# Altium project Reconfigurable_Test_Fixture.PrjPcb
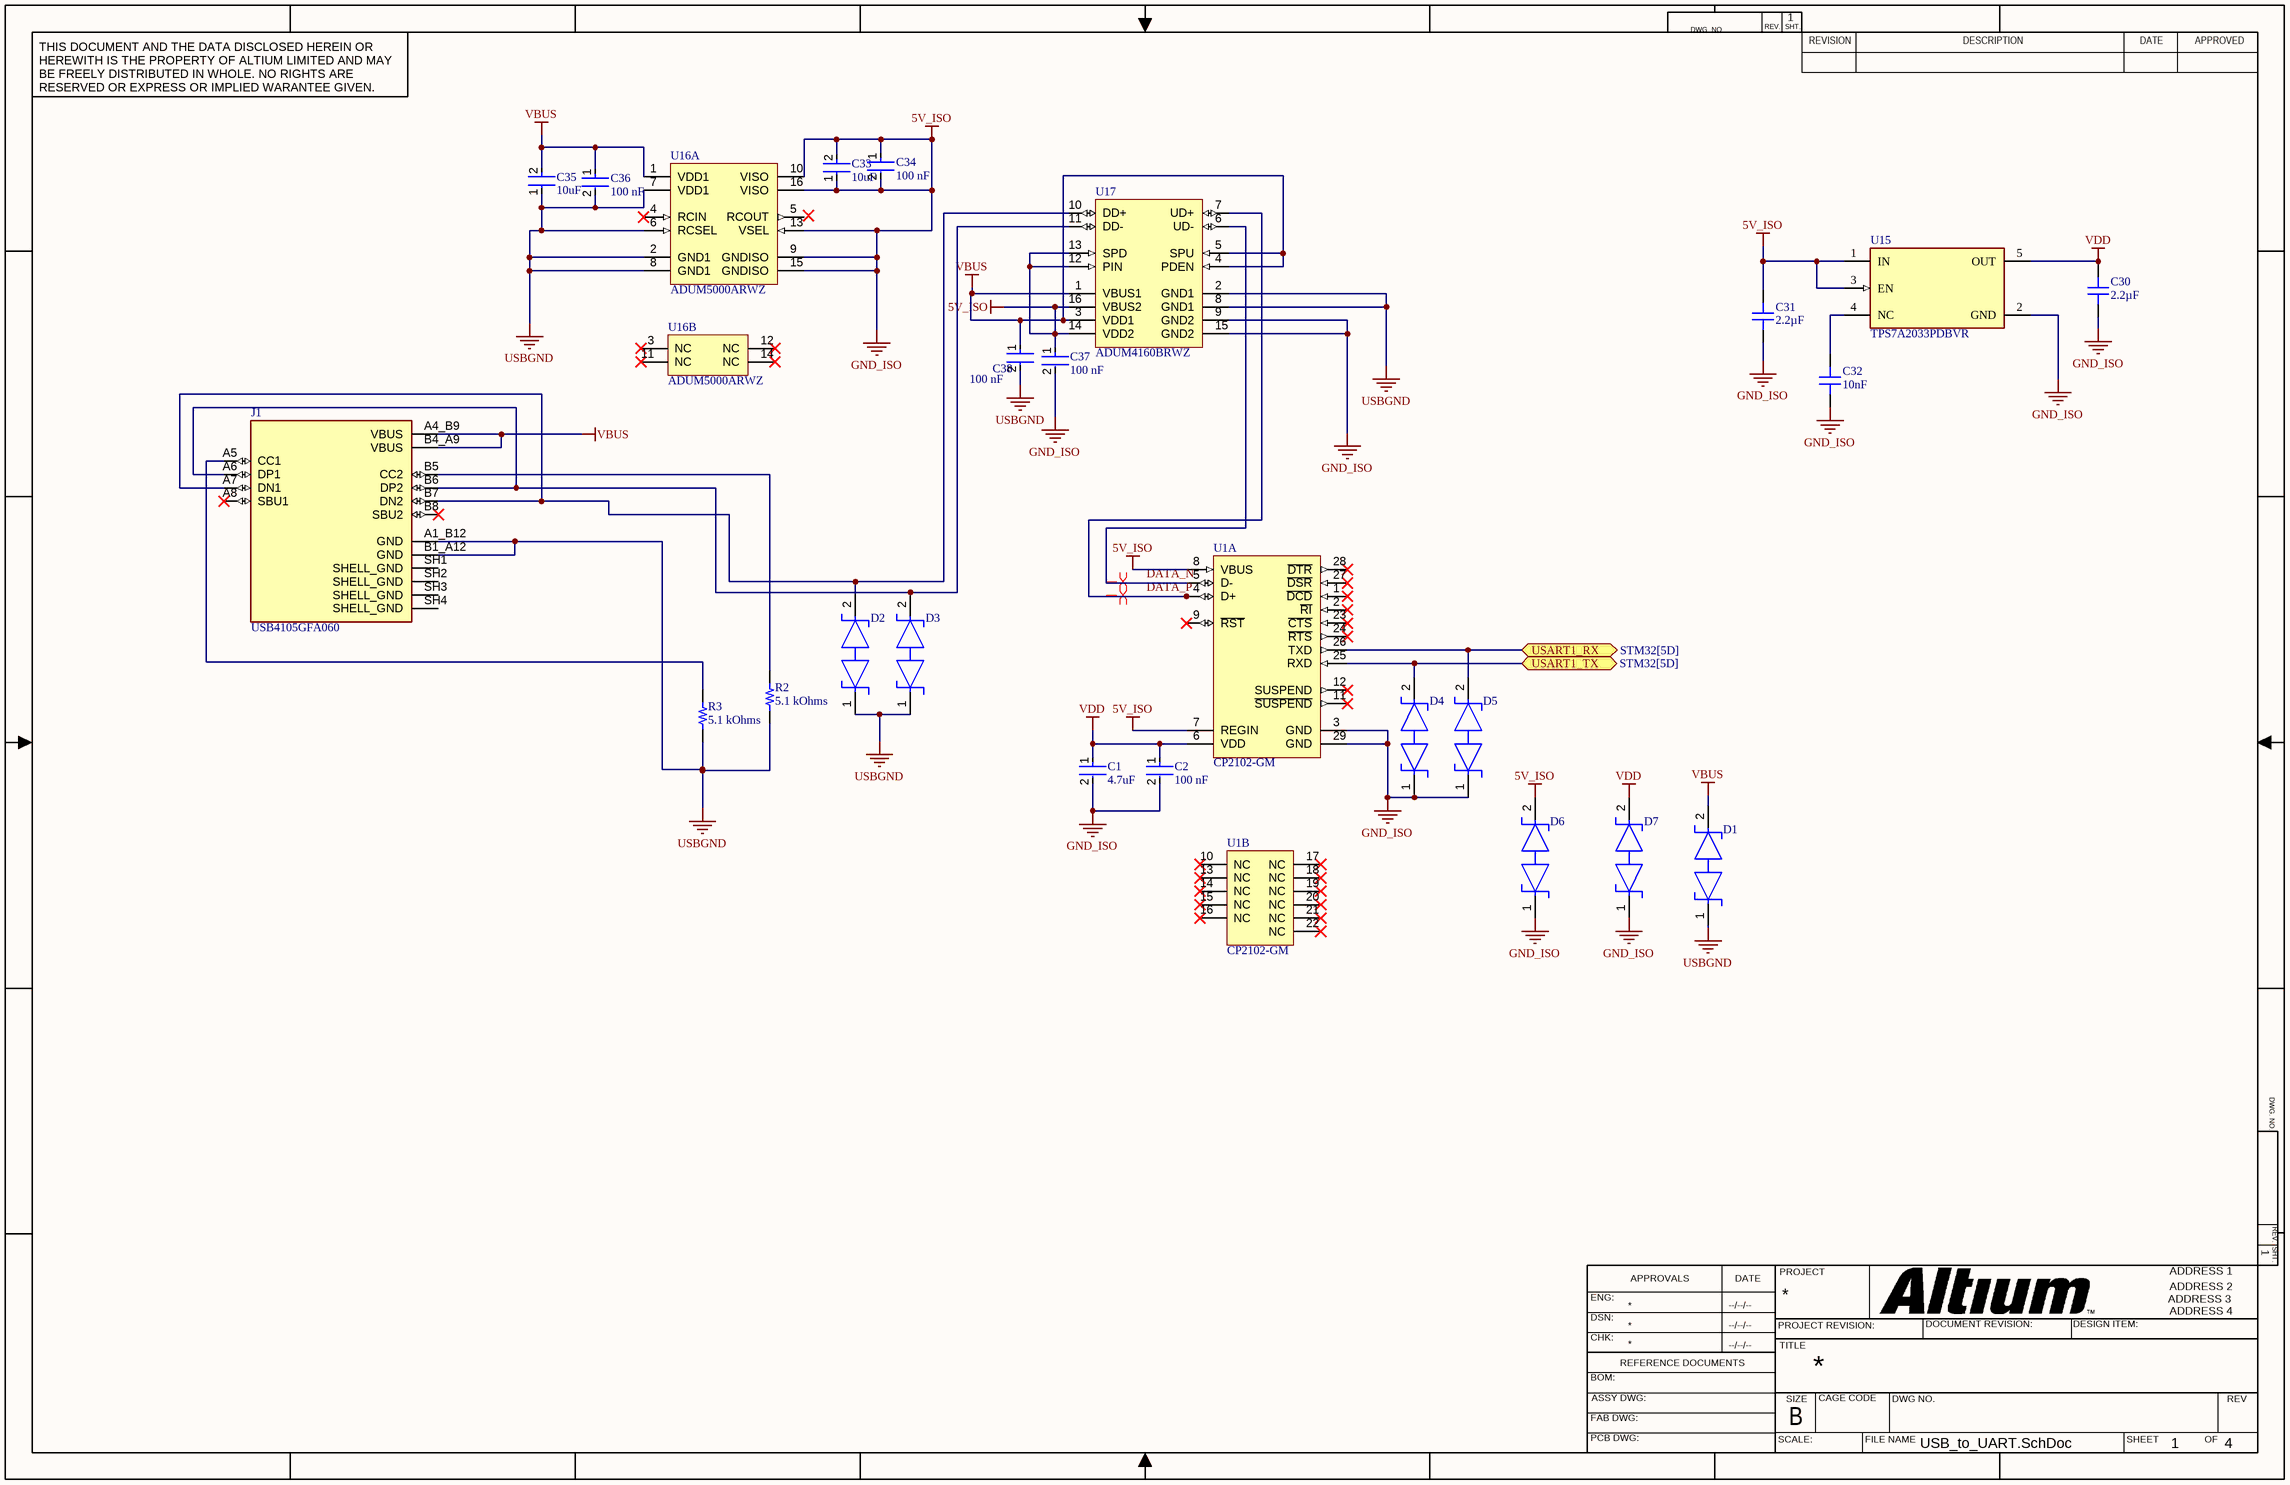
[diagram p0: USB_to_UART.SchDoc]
4 sheets, 89 parts. Net scope: flat (ports and power ports of the same name join across sheets).
Sheets:
  USB_to_UART.SchDoc
  STM32.SchDoc
  Analog_Switch_Array_and_ZIF_ socket.SchDoc
  Muxes_and_ADC.SchDoc

## Sheet USB_to_UART.SchDoc
size 431 x 279 mm; Organization: ORGANIZATION; Address1: ADDRESS 1; Address2: ADDRESS 2; Address3: ADDRESS 3; Address4: ADDRESS 4; Revision: -; SheetNumber: 1; SheetTotal: 4; ENG_APP_DATE: --/--/--; DSN_APP_DATE: --/--/--; CHK_APP_DATE: --/--/--

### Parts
C1  4.7uF  [FP-C1005-050-0_15-IPC_C]
C2  100 nF  [FP-CC0402-MFG]
C30  value 2.2µF  [MURATA GRM155 0402_1005]  (hidden comment: GRM155C81C105ME11J)
C31  value 2.2µF  [MURATA GRM155 0402_1005]  (hidden comment: GRM155C81C105ME11J)
C32  value 10nF  [MURATA GRM155 0402_1005]  (hidden comment: GRM155C81C105ME11J)
C33  10uF  [FP-C1608-080-0_1-MFG]
C34  100 nF  [FP-CC0402-MFG]
C35  10uF  [FP-C1608-080-0_1-MFG]
C36  100 nF  [FP-CC0402-MFG]
C37  100 nF  [FP-CC0402-MFG]
C38  100 nF  [FP-CC0402-MFG]
D1  TPD1E10B06DPYR  [FP-DPY0002A-MFG]  (value not drawn)
D2  TPD1E10B06DPYR  [FP-DPY0002A-MFG]  (value not drawn)
D3  TPD1E10B06DPYR  [FP-DPY0002A-MFG]  (value not drawn)
D4  TPD1E10B06DPYR  [FP-DPY0002A-MFG]  (value not drawn)
D5  TPD1E10B06DPYR  [FP-DPY0002A-MFG]  (value not drawn)
D6  TPD1E10B06DPYR  [FP-DPY0002A-MFG]  (value not drawn)
D7  TPD1E10B06DPYR  [FP-DPY0002A-MFG]  (value not drawn)
J1  USB4105GFA060  [GCT_USB4105GFA060]
R2  value 5.1 kOhms  [YAGEO RES 0603_1608]  (hidden comment: RC0603JR-105K1L)
R3  value 5.1 kOhms  [YAGEO RES 0603_1608]  (hidden comment: RC0603JR-105K1L)
U1  CP2102-GM  [SLAB-QFN-28-3125x3125TP_N]  (parts A,B of 2)
U15  TPS7A2033PDBVR  [FP-DBV0005A-MFG]
U16  ADUM5000ARWZ  [ADI-RW-16_N]  (parts A,B of 2)
U17  ADUM4160BRWZ  [RW-16_L]

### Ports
USART1_RX (bidir, see STM32[5D]), USART1_TX (bidir, see STM32[5D])

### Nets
5V_ISO: C1.2 C2.2 C30.1 C31.1 C31.2 C32.1 C33.1 C33.2 C34.1 C34.2 C37.1 C37.2 D4.1 D5.1 D6.1 D6.2 D7.1 U1.3(GND) U1.7(REGIN) U1.8(VBUS) U1.29(GND) U15.1(IN) U15.2(GND) U15.3(EN) U16.9(GNDISO) U16.10(VISO) U16.13(VSEL) U16.15(GNDISO) U16.16(VISO) U17.9(GND2) U17.12(PIN) U17.13(SPD) U17.14(VDD2) U17.15(GND2) U17.16(VBUS2)  [also labelled GND_ISO]
USBGND: C35.1 C36.2 C38.2 D1.1 D2.1 D3.1 J1.A1_B12(GND) J1.B1_A12(GND) R2.1 R3.1 U16.2(GND1) U16.6(RCSEL) U16.7(VDD1) U16.8(GND1) U17.2(GND1) U17.8(GND1)
VBUS: C35.2 C36.1 C38.1 D1.2 J1.A4_B9(VBUS) J1.B4_A9(VBUS) U16.1(VDD1) U17.1(VBUS1) U17.3(VDD1) U17.4(PDEN) U17.5(SPU)
VDD: C1.1 C2.1 C30.2 D7.2 U1.6(VDD) U15.5(OUT)
NetC32_2: C32.2 U15.4(NC)
NetD2_2: D2.2 J1.A7(DN1) J1.B7(DN2) U17.10(DD+)
NetD3_2: D3.2 J1.A6(DP1) J1.B6(DP2) U17.11(DD-)
NetD4_2: D4.2 U1.25(RXD) ; port USART1_TX
NetD5_2: D5.2 U1.26(TXD) ; port USART1_RX
NetJ1_A5: J1.A5(CC1) R3.2
NetJ1_B5: J1.B5(CC2) R2.2
NetU1_4: U1.4(D+) U17.7(UD+)
NetU1_5: U1.5(D-) U17.6(UD-)

Not connected (* = marked no-connect by the designer): J1 A8(SBU1)* B8(SBU2)* SH1(SHELL_GND) SH2(SHELL_GND) SH3(SHELL_GND) SH4(SHELL_GND); U1 1(~{DCD})* 2(~{RI})* 9(~{RST})* 10(NC)* 11(~{SUSPEND})* 12(SUSPEND)* 13(NC)* 14(NC)* 15(NC)* 16(NC)* 17(NC)* 18(NC)* 19(NC)* 20(NC)* 21(NC)* 22(NC)* 23(~{CTS})* 24(~{RTS})* 27(~{DSR})* 28(~{DTR})*; U16 3(NC)* 4(RCIN)* 5(RCOUT) 11(NC)* 12(NC)* 14(NC)*

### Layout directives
differential pair: (no net found under the mark), NetU1_5

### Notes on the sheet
- Labels drawn without touching a wire or pin: DATA_N, DATA_P

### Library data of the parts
C1 = CMP-2000-05997-2: CAP CER 4.7UF 10V X5R 0402; Manufacturer: TDK; PartNumber: C1005X5R1A475K050BC; Dielectric Material: Ceramic; Tolerance: 10%
C2 C34 C36-C38 = CMP-03422-000048-1: CAP CER 0.1UF 16V X7R 0402; Manufacturer: YAGEO; PartNumber: CC0402KRX7R7BB104; Material: Ceramic; Automotive Grade: NA; Temperature Coefficient: 30ppm/°C; Tolerance: 0.1
C30-C32 = CMP-001-034252-1: CAP CER 1UF 16V X6S 0402
C33 C35 = CMP-2000-04979-3: Multilayer Ceramic Capacitors 10μF ±10% 10V X5R SMD 0603; PartNumber: C1608X5R1A106K080AC; Manufacturer: TDK
D1-D7 = CMP-0326-00004-4: TVS DIODE 5.5V 14V 2X1SON; Manufacturer: Texas Instruments; Leakage Current: 100nA; Min Breakdown Voltage: 6V; Number of Channels: 1; ESD Protection: Yes; Power Line Protection: No; Test Current: 1mA; Interface: GPIO; Element Configuration: Single; Peak Pulse Current: 5A; Direction: Bidirectional; Peak Pulse Power: 90W; Capacitance: 12pF
J1 = CMP-002-00267-1: USB-C (USB TYPE-C) USB 2.0 Receptacle Connector 24 (16+8 Dummy) Position Surface Mount, Right Angle; Through Hole; MF: Global Connector Technology
R2 R3 = CMP-009-046115-1: RES 5.1K OHM 5% 1/10W 0603
U1 = CMP-0511-00012-1: Single-Chip USB to UART Bridge, 1024 Bytes EEPROM, -40 to 85 degC, 28-pin QFN, Tube; Manufacturer: Silicon Labs; Internal Oscillator: TRUE; Sub-Family: USB Bridges
U15 = CMP-04917-000300-1: IC REG LINEAR 3.3V 300MA SOT23-5
U16 = CMP-0534-00437-1: Isolated DC / DC Converter, 2.5 KV rms Insulation Rating, Industrial, 16-pin SOIC (RW-16), Tube; Manufacturer: Analog Devices; Insulation Rating (kVrms): 2.5
U17 = CMP-0534-00647-1: Full/Low Speed USB Digital Isolator, 2 Channels, 5 kV rms, 3.1 to 5.5 V, -40 to 105 degC, 16-Pin SOIC (RW-16), RoHS, Tube; Manufacturer: Analog Devices; IDD@12 Mbps: 8 mA Max.; Number of Channels: 2; Data Rate: 12 Mbps Max.; CIN: 10 pF Typ.; Voltage Isolation: 5 kVrms

## Sheet STM32.SchDoc
size 431 x 279 mm; SheetNumber: 2; SheetTotal: 4
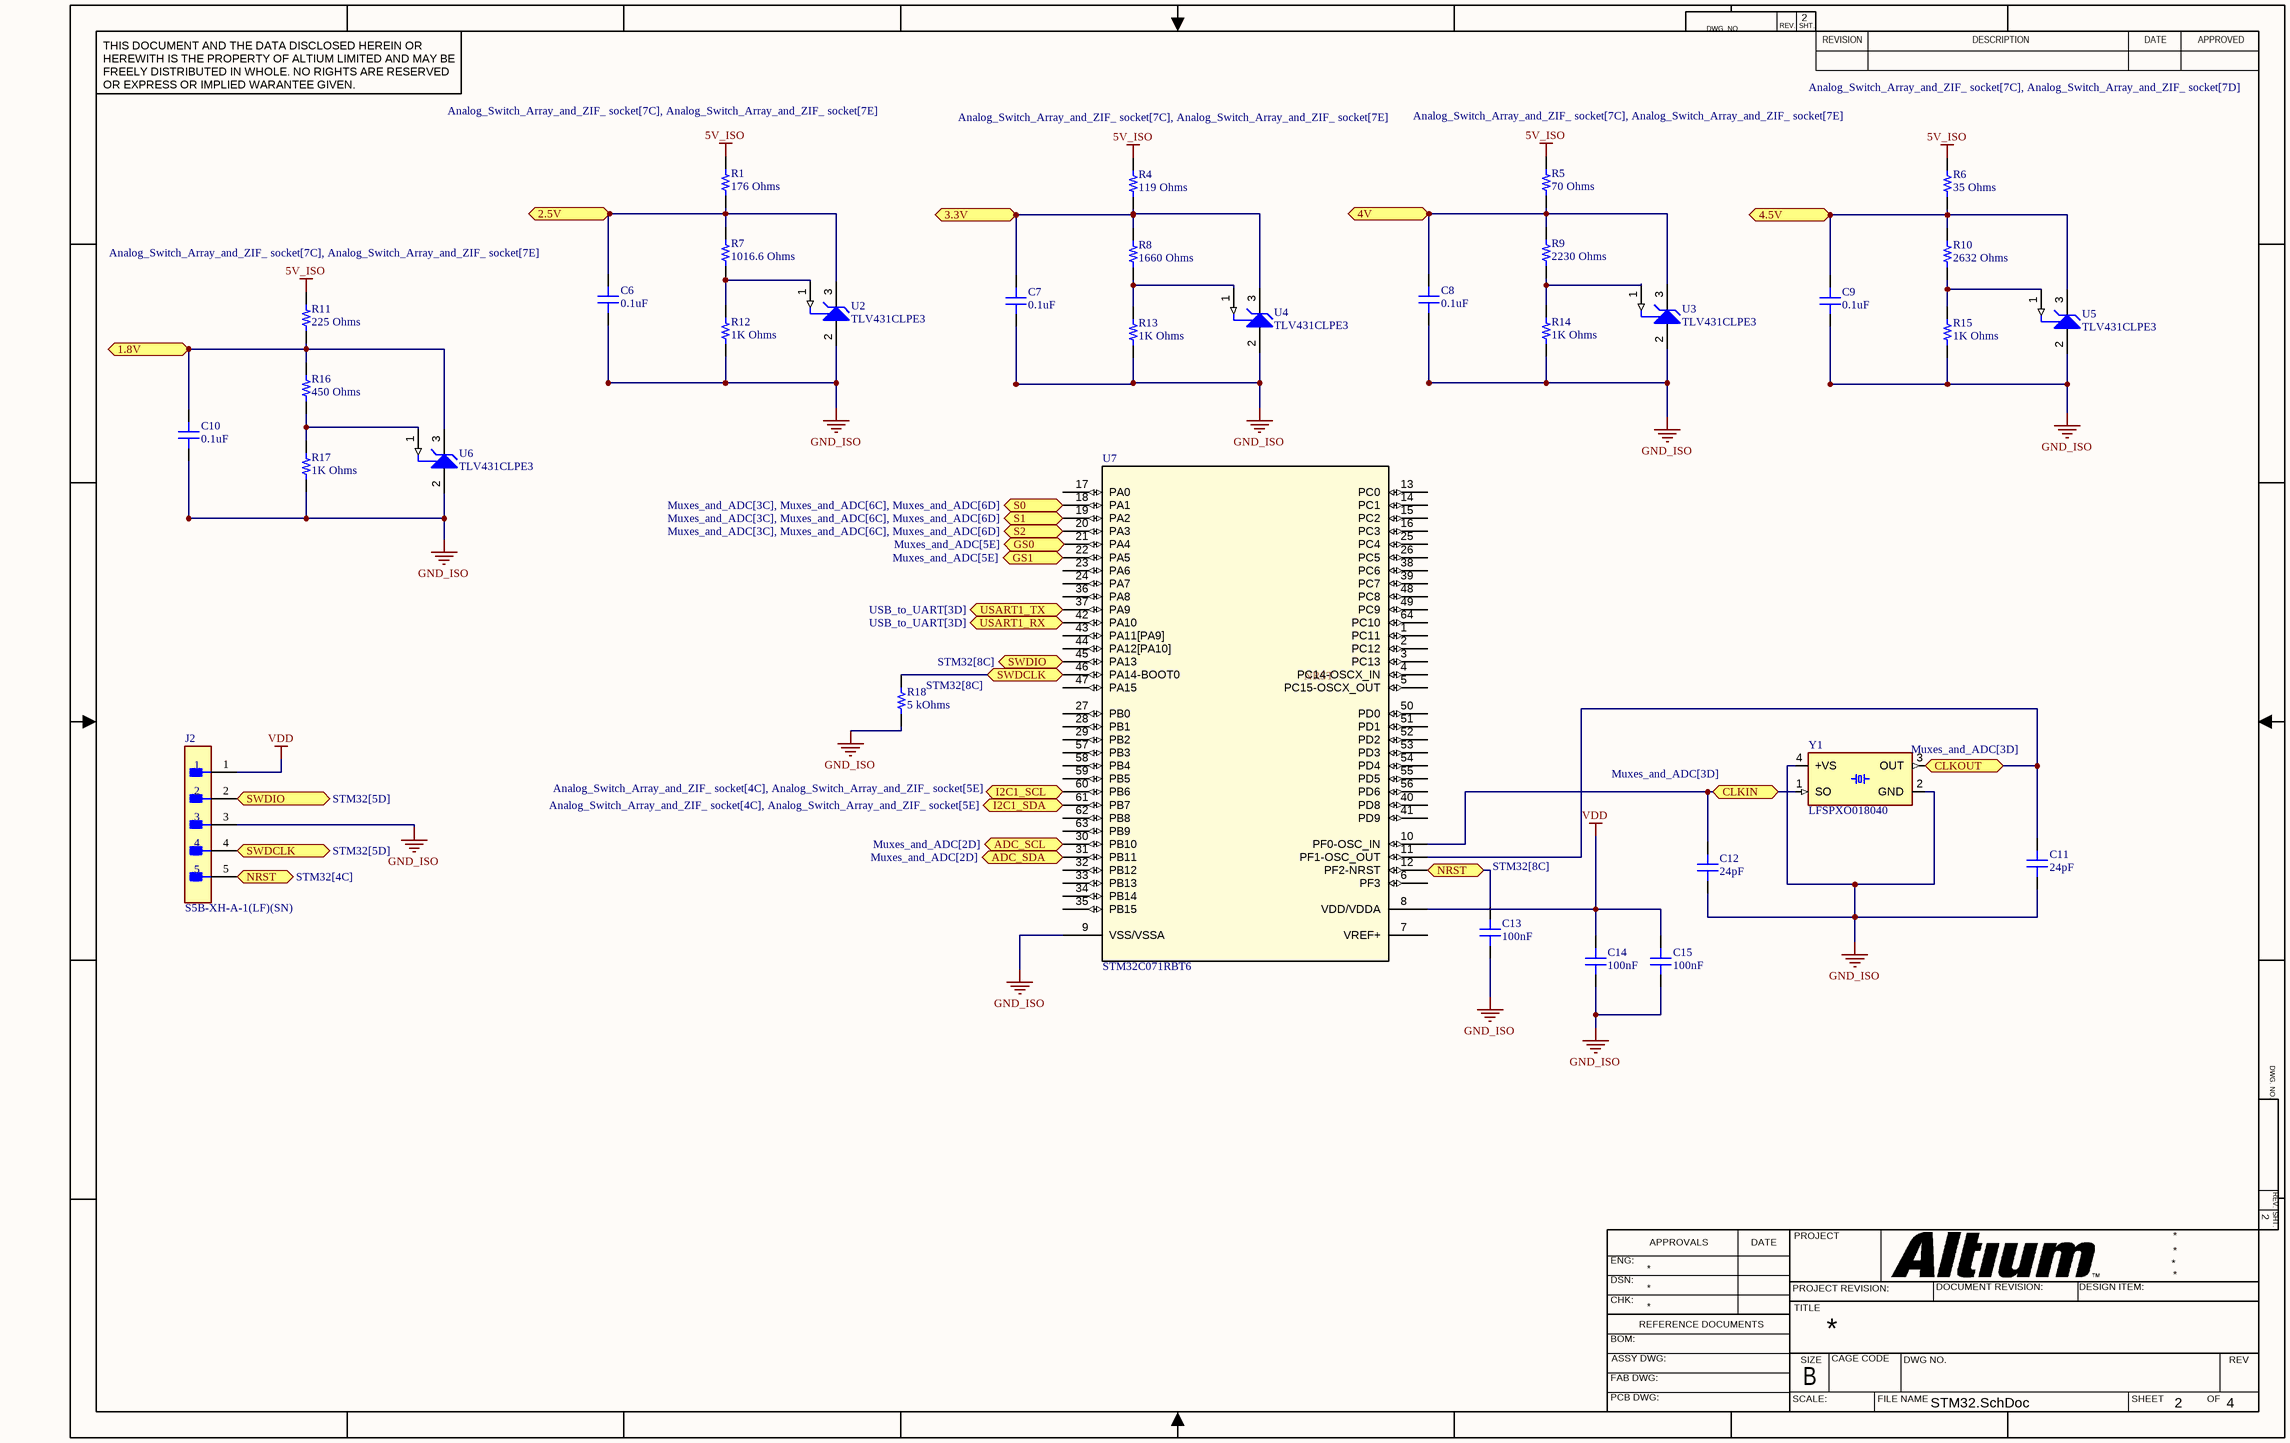
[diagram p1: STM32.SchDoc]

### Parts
C6  value 0.1uF  [MURATA GRM155 0402_1005]  (hidden comment: GRM155R71H104KE14D)
C7  value 0.1uF  [MURATA GRM155 0402_1005]  (hidden comment: GRM155R71H104KE14D)
C8  value 0.1uF  [MURATA GRM155 0402_1005]  (hidden comment: GRM155R71H104KE14D)
C9  value 0.1uF  [MURATA GRM155 0402_1005]  (hidden comment: GRM155R71H104KE14D)
C10  value 0.1uF  [MURATA GRM155 0402_1005]  (hidden comment: GRM155R71H104KE14D)
C11  value 24pF  [MURATA GRM155 0402_1005]  (hidden comment: GRM155R71H104KE14D)
C12  value 24pF  [MURATA GRM155 0402_1005]  (hidden comment: GRM155R71H104KE14D)
C13  value 100nF  [MURATA GRM155 0402_1005]  (hidden comment: GRM155R71H104KE14D)
C14  value 100nF  [MURATA GRM155 0402_1005]  (hidden comment: GRM155R71H104KE14D)
C15  value 100nF  [MURATA GRM155 0402_1005]  (hidden comment: GRM155R71H104KE14D)
J2  S5B-XH-A-1(LF)(SN)  [FP-S5B-XH-A-1_LF_SN-MFG]
R1  value 176 Ohms  [RES 0805_2012]  (hidden comment: RMEF0805FT200R)
R4  value 119 Ohms  [RES 0805_2012]  (hidden comment: RMEF0805FT200R)
R5  value 70 Ohms  [RES 0805_2012]  (hidden comment: RMEF0805FT200R)
R6  value 35 Ohms  [RES 0805_2012]  (hidden comment: RMEF0805FT200R)
R7  value 1016.6 Ohms  [RES 0805_2012]  (hidden comment: RMEF0805FT200R)
R8  value 1660 Ohms  [RES 0805_2012]  (hidden comment: RMEF0805FT200R)
R9  value 2230 Ohms  [RES 0805_2012]  (hidden comment: RMEF0805FT200R)
R10  value 2632 Ohms  [RES 0805_2012]  (hidden comment: RMEF0805FT200R)
R11  value 225 Ohms  [RES 0805_2012]  (hidden comment: RMEF0805FT200R)
R12  value 1K Ohms  [RES 0805_2012]  (hidden comment: RMEF0805FT200R)
R13  value 1K Ohms  [RES 0805_2012]  (hidden comment: RMEF0805FT200R)
R14  value 1K Ohms  [RES 0805_2012]  (hidden comment: RMEF0805FT200R)
R15  value 1K Ohms  [RES 0805_2012]  (hidden comment: RMEF0805FT200R)
R16  value 450 Ohms  [RES 0805_2012]  (hidden comment: RMEF0805FT200R)
R17  value 1K Ohms  [RES 0805_2012]  (hidden comment: RMEF0805FT200R)
R18  value 5 kOhms  [RES 0603_1608]  (hidden comment: PNM0603E5001BST5)
U2  TLV431CLPE3  [TI-LP3]
U3  TLV431CLPE3  [TI-LP3]
U4  TLV431CLPE3  [TI-LP3]
U5  TLV431CLPE3  [TI-LP3]
U6  TLV431CLPE3  [TI-LP3]
U7  STM32C071RBT6  [LQFP-64_STM]
Y1  LFSPXO018040  [WE-SPXO_LFSPXO018040]

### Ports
1.8V (bidir, see Analog_Switch_Array_and_ZIF_ socket[7C], Analog_Switch_Array_and_ZIF_ socket[7E]), 2.5V (bidir, see Analog_Switch_Array_and_ZIF_ socket[7C], Analog_Switch_Array_and_ZIF_ socket[7E]), 3.3V (bidir, see Analog_Switch_Array_and_ZIF_ socket[7C], Analog_Switch_Array_and_ZIF_ socket[7E]), 4.5V (bidir, see Analog_Switch_Array_and_ZIF_ socket[7C], Analog_Switch_Array_and_ZIF_ socket[7D]), 4V (bidir, see Analog_Switch_Array_and_ZIF_ socket[7C], Analog_Switch_Array_and_ZIF_ socket[7E]), ADC_SCL (bidir, see Muxes_and_ADC[2D]), ADC_SDA (bidir, see Muxes_and_ADC[2D]), CLKIN (bidir, see Muxes_and_ADC[3D]), CLKOUT (bidir, see Muxes_and_ADC[3D]), GS0 (bidir, see Muxes_and_ADC[5E]), GS1 (bidir, see Muxes_and_ADC[5E]), I2C1_SCL (bidir, see Analog_Switch_Array_and_ZIF_ socket[4C], Analog_Switch_Array_and_ZIF_ socket[5E]), I2C1_SDA (bidir, see Analog_Switch_Array_and_ZIF_ socket[4C], Analog_Switch_Array_and_ZIF_ socket[5E]), NRST (bidir, see STM32[4C]), NRST (bidir, see STM32[8C]), S0 (bidir, see Muxes_and_ADC[3C], Muxes_and_ADC[6C], Muxes_and_ADC[6D]), S1 (bidir, see Muxes_and_ADC[3C], Muxes_and_ADC[6C], Muxes_and_ADC[6D]), S2 (bidir, see Muxes_and_ADC[3C], Muxes_and_ADC[6C], Muxes_and_ADC[6D]), SWDCLK (bidir, see STM32[5D]), SWDCLK (bidir, see STM32[8C]), SWDIO (bidir, see STM32[5D]), SWDIO (bidir, see STM32[8C]), USART1_RX (bidir, see USB_to_UART[3D]), USART1_TX (bidir, see USB_to_UART[3D])

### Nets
5V_ISO: C6.1 C7.1 C8.1 C9.1 C10.1 C11.1 C12.1 C13.1 C14.1 C15.1 J2.3 R1.1 R4.1 R5.1 R6.1 R11.1 R12.1 R13.1 R14.1 R15.1 R17.1 R18.1 U2.2(ANODE) U3.2(ANODE) U4.2(ANODE) U5.2(ANODE) U6.2(ANODE) U7.9(VSS/VSSA) Y1.2(GND) Y1.4(+VS)  [also labelled GND_ISO]
VDD: C14.2 C15.2 J2.1 U7.8(VDD/VDDA)
NetC6_2: C6.2 R1.2 R7.2 U2.3(CATHODE) ; port 2.5V
NetC7_2: C7.2 R4.2 R8.2 U4.3(CATHODE) ; port 3.3V
NetC8_2: C8.2 R5.2 R9.2 U3.3(CATHODE) ; port 4V
NetC9_2: C9.2 R6.2 R10.2 U5.3(CATHODE) ; port 4.5V
NetC10_2: C10.2 R11.2 R16.2 U6.3(CATHODE) ; port 1.8V
NetC11_2: C11.2 U7.11(PF1-OSC_OUT) Y1.3(OUT) ; port CLKOUT
NetC12_2: C12.2 U7.10(PF0-OSC_IN) Y1.1(SO) ; port CLKIN
NetC13_2: C13.2 J2.5 U7.12(PF2-NRST) ; port NRST
NetD4_2: U7.37(PA9) ; port USART1_TX
NetD5_2: U7.42(PA10) ; port USART1_RX
NetJ2_2: J2.2 U7.45(PA13) ; port SWDIO
NetJ2_4: J2.4 R18.2 U7.46(PA14-BOOT0) ; port SWDCLK
NetR7_1: R7.1 R12.2 U2.1(REF)
NetR8_1: R8.1 R13.2 U4.1(REF)
NetR9_1: R9.1 R14.2 U3.1(REF)
NetR10_1: R10.1 R15.2 U5.1(REF)
NetR16_1: R16.1 R17.2 U6.1(REF)
NetR20_1: U7.60(PB6) ; port I2C1_SCL
NetR20_2: U7.61(PB7) ; port I2C1_SDA
NetR25_2: U7.30(PB10) ; port ADC_SCL
NetR26_2: U7.31(PB11) ; port ADC_SDA
NetU7_18: U7.18(PA1) ; port S0
NetU7_19: U7.19(PA2) ; port S1
NetU7_20: U7.20(PA3) ; port S2
NetU7_22: U7.22(PA5) ; port GS1

Not connected (* = marked no-connect by the designer): U7 1(PC11) 2(PC12) 3(PC13) 4(PC14-OSCX_IN) 5(PC15-OSCX_OUT) 6(PF3) 7(VREF+) 13(PC0) 14(PC1) 15(PC2) 16(PC3) 17(PA0) 21(PA4) 23(PA6) 24(PA7) 25(PC4) 26(PC5) 27(PB0) 28(PB1) 29(PB2) 32(PB12) 33(PB13) 34(PB14) 35(PB15) 36(PA8) 38(PC6) 39(PC7) 40(PD8) 41(PD9) 43(PA11[PA9]) 44(PA12[PA10]) 47(PA15) 48(PC8) 49(PC9) 50(PD0) 51(PD1) 52(PD2) 53(PD3) 54(PD4) 55(PD5) 56(PD6) 57(PB3) 58(PB4) 59(PB5) 62(PB8) 63(PB9) 64(PC10)

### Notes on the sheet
- Labels drawn without touching a wire or pin: NRST

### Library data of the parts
C6-C15 = CMP-001-031367-1: CAP CER 0.1UF 50V X7R 0402
J2 = CMP-17439-000362-1: CONN HEADER R/A 5POS 2.5MM; Number of Positions: 5; Voltage Rating: 250V
R1 R4-R17 = CMP-009-068802-1: RES 200 OHM 1% 1/8W 0805
R18 = CMP-009-033475-1: RES SMD 5K OHM 0.1% 0.15W 0603
U2-U6 = CMP-0366-00210-1: Low Voltage Adjustable Precision Shunt Regulator, 39 ppm / degC, 15 mA, 0 to 70 degC, 3-pin TO-92 (LP), Pb-Free (RoHS); Manufacturer: Texas Instruments; Eco-Plan: Green (RoHS & no Sb/Br); Iout/Iz(Max)(mA): 15; VO Adj(Max)(V): 6; Min Iz for Regulation(uA): 80; SubFamily: Shunt Voltage Reference; VO Adj(Min)(V): 1.24; Rating: Catalog; Temp Coeff(Typ)(ppm/ degree C): 39; Initial Accuracy @ 25/deg C(%): 1.5; Temp Coeff(Max)(ppm/ degree C): 129
U7 = CMP-031-00033-1: Mainstream Arm Cortex-M0+ MCU with 128 Kbytes of Flash memory, 24 Kbytes RAM, 48 MHz CPU, 2x USART, timers, ADC, comm. I/F, USB FS, 2-3.6V; Manufacturer_Name: STMicroelectronics
Y1 = CMP-574-000000-1: MF: IQD Frequency Products

## Sheet Analog_Switch_Array_and_ZIF_ socket.SchDoc
size 431 x 279 mm; Organization: ORGANIZATION; Address1: ADDRESS 1; Address2: ADDRESS 2; Address3: ADDRESS 3; Address4: ADDRESS 4; Revision: -; SheetNumber: 3; SheetTotal: 4; ENG_APP_DATE: --/--/--; DSN_APP_DATE: --/--/--; CHK_APP_DATE: --/--/--
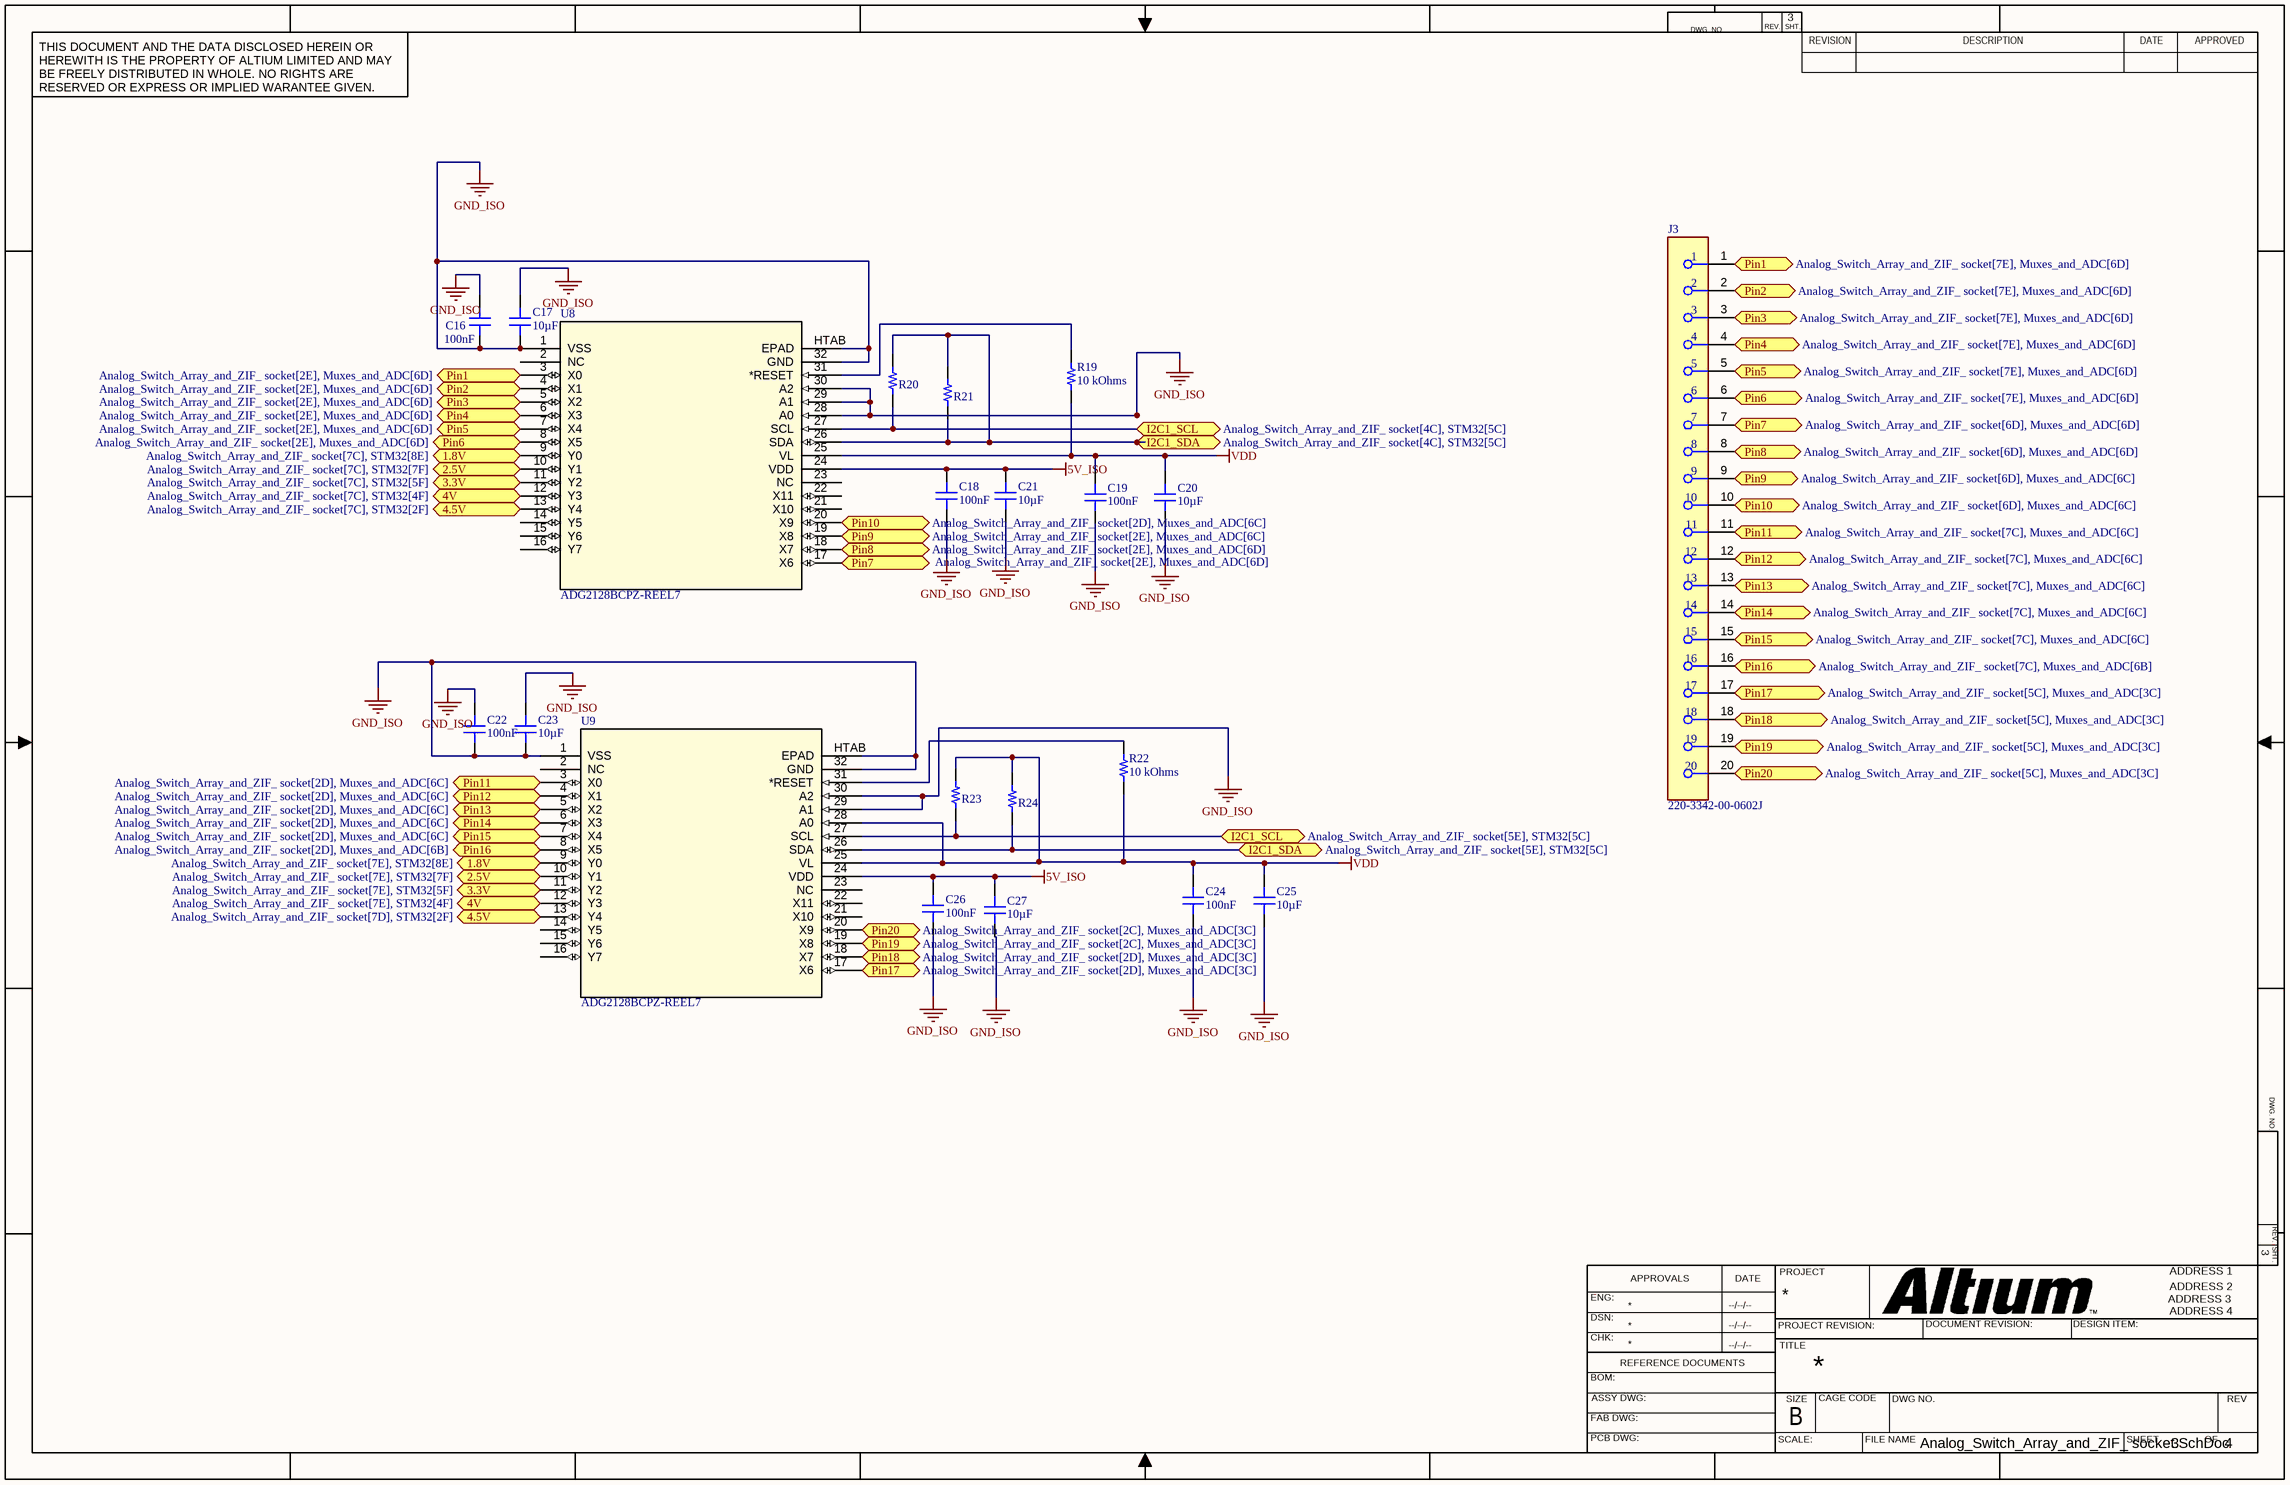
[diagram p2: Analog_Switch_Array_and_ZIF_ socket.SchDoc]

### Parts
C16  value 100nF  [CAP 1206_3216 - 0.8MM]  (hidden comment: C1206X104G4HAC7800)
C17  value 10µF  [CAP 0603_1608]  (hidden comment: KGM15CR51A106MM)
C18  value 100nF  [CAP 1206_3216 - 0.8MM]  (hidden comment: C1206X104G4HAC7800)
C19  value 100nF  [CAP 1206_3216 - 0.8MM]  (hidden comment: C1206X104G4HAC7800)
C20  value 10µF  [CAP 0603_1608]  (hidden comment: KGM15CR51A106MM)
C21  value 10µF  [CAP 0603_1608]  (hidden comment: KGM15CR51A106MM)
C22  value 100nF  [CAP 1206_3216 - 0.8MM]  (hidden comment: C1206X104G4HAC7800)
C23  value 10µF  [CAP 0603_1608]  (hidden comment: KGM15CR51A106MM)
C24  value 100nF  [CAP 1206_3216 - 0.8MM]  (hidden comment: C1206X104G4HAC7800)
C25  value 10µF  [CAP 0603_1608]  (hidden comment: KGM15CR51A106MM)
C26  value 100nF  [CAP 1206_3216 - 0.8MM]  (hidden comment: C1206X104G4HAC7800)
C27  value 10µF  [CAP 0603_1608]  (hidden comment: KGM15CR51A106MM)
J3  220-3342-00-0602J  [FP-220-3342-00-0602J-0]
R19  value 10 kOhms  [RES 0402_1005]  (hidden comment: RP73PF1E10KBTDF)
R20  SG732ETTD222K  [RES 1210_3225]  (value not drawn)
R21  SG732ETTD222K  [RES 1210_3225]  (value not drawn)
R22  value 10 kOhms  [RES 0402_1005]  (hidden comment: RP73PF1E10KBTDF)
R23  SG732ETTD222K  [RES 1210_3225]  (value not drawn)
R24  SG732ETTD222K  [RES 1210_3225]  (value not drawn)
U8  ADG2128BCPZ-REEL7  [CP_32_7_ADI]
U9  ADG2128BCPZ-REEL7  [CP_32_7_ADI]

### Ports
1.8V (bidir, see Analog_Switch_Array_and_ZIF_ socket[7C], STM32[8E]), 1.8V (bidir, see Analog_Switch_Array_and_ZIF_ socket[7E], STM32[8E]), 2.5V (bidir, see Analog_Switch_Array_and_ZIF_ socket[7C], STM32[7F]), 2.5V (bidir, see Analog_Switch_Array_and_ZIF_ socket[7E], STM32[7F]), 3.3V (bidir, see Analog_Switch_Array_and_ZIF_ socket[7C], STM32[5F]), 3.3V (bidir, see Analog_Switch_Array_and_ZIF_ socket[7E], STM32[5F]), 4.5V (bidir, see Analog_Switch_Array_and_ZIF_ socket[7C], STM32[2F]), 4.5V (bidir, see Analog_Switch_Array_and_ZIF_ socket[7D], STM32[2F]), 4V (bidir, see Analog_Switch_Array_and_ZIF_ socket[7C], STM32[4F]), 4V (bidir, see Analog_Switch_Array_and_ZIF_ socket[7E], STM32[4F]), I2C1_SCL (bidir, see Analog_Switch_Array_and_ZIF_ socket[4C], STM32[5C]), I2C1_SCL (bidir, see Analog_Switch_Array_and_ZIF_ socket[5E], STM32[5C]), I2C1_SDA (bidir, see Analog_Switch_Array_and_ZIF_ socket[4C], STM32[5C]), I2C1_SDA (bidir, see Analog_Switch_Array_and_ZIF_ socket[5E], STM32[5C]), Pin1 (bidir, see Analog_Switch_Array_and_ZIF_ socket[2E], Muxes_and_ADC[6D]), Pin1 (bidir, see Analog_Switch_Array_and_ZIF_ socket[7E], Muxes_and_ADC[6D]), Pin2 (bidir, see Analog_Switch_Array_and_ZIF_ socket[2E], Muxes_and_ADC[6D]), Pin2 (bidir, see Analog_Switch_Array_and_ZIF_ socket[7E], Muxes_and_ADC[6D]), Pin3 (bidir, see Analog_Switch_Array_and_ZIF_ socket[2E], Muxes_and_ADC[6D]), Pin3 (bidir, see Analog_Switch_Array_and_ZIF_ socket[7E], Muxes_and_ADC[6D]), Pin4 (bidir, see Analog_Switch_Array_and_ZIF_ socket[2E], Muxes_and_ADC[6D]), Pin4 (bidir, see Analog_Switch_Array_and_ZIF_ socket[7E], Muxes_and_ADC[6D]), Pin5 (bidir, see Analog_Switch_Array_and_ZIF_ socket[2E], Muxes_and_ADC[6D]), Pin5 (bidir, see Analog_Switch_Array_and_ZIF_ socket[7E], Muxes_and_ADC[6D]), Pin6 (bidir, see Analog_Switch_Array_and_ZIF_ socket[2E], Muxes_and_ADC[6D]), Pin6 (bidir, see Analog_Switch_Array_and_ZIF_ socket[7E], Muxes_and_ADC[6D]), Pin7 (bidir, see Analog_Switch_Array_and_ZIF_ socket[2E], Muxes_and_ADC[6D]), Pin7 (bidir, see Analog_Switch_Array_and_ZIF_ socket[6D], Muxes_and_ADC[6D]), Pin8 (bidir, see Analog_Switch_Array_and_ZIF_ socket[2E], Muxes_and_ADC[6D]), Pin8 (bidir, see Analog_Switch_Array_and_ZIF_ socket[6D], Muxes_and_ADC[6D]), Pin9 (bidir, see Analog_Switch_Array_and_ZIF_ socket[2E], Muxes_and_ADC[6C]), Pin9 (bidir, see Analog_Switch_Array_and_ZIF_ socket[6D], Muxes_and_ADC[6C]), Pin10 (bidir, see Analog_Switch_Array_and_ZIF_ socket[2D], Muxes_and_ADC[6C]), Pin10 (bidir, see Analog_Switch_Array_and_ZIF_ socket[6D], Muxes_and_ADC[6C]), Pin11 (bidir, see Analog_Switch_Array_and_ZIF_ socket[2D], Muxes_and_ADC[6C]), Pin11 (bidir, see Analog_Switch_Array_and_ZIF_ socket[7C], Muxes_and_ADC[6C]), Pin12 (bidir, see Analog_Switch_Array_and_ZIF_ socket[2D], Muxes_and_ADC[6C]), Pin12 (bidir, see Analog_Switch_Array_and_ZIF_ socket[7C], Muxes_and_ADC[6C]), Pin13 (bidir, see Analog_Switch_Array_and_ZIF_ socket[2D], Muxes_and_ADC[6C]), Pin13 (bidir, see Analog_Switch_Array_and_ZIF_ socket[7C], Muxes_and_ADC[6C]), Pin14 (bidir, see Analog_Switch_Array_and_ZIF_ socket[2D], Muxes_and_ADC[6C]), Pin14 (bidir, see Analog_Switch_Array_and_ZIF_ socket[7C], Muxes_and_ADC[6C]), Pin15 (bidir, see Analog_Switch_Array_and_ZIF_ socket[2D], Muxes_and_ADC[6C]), Pin15 (bidir, see Analog_Switch_Array_and_ZIF_ socket[7C], Muxes_and_ADC[6C]), Pin16 (bidir, see Analog_Switch_Array_and_ZIF_ socket[2D], Muxes_and_ADC[6B]), Pin16 (bidir, see Analog_Switch_Array_and_ZIF_ socket[7C], Muxes_and_ADC[6B]), Pin17 (bidir, see Analog_Switch_Array_and_ZIF_ socket[2D], Muxes_and_ADC[3C]), Pin17 (bidir, see Analog_Switch_Array_and_ZIF_ socket[5C], Muxes_and_ADC[3C]), Pin18 (bidir, see Analog_Switch_Array_and_ZIF_ socket[2D], Muxes_and_ADC[3C]), Pin18 (bidir, see Analog_Switch_Array_and_ZIF_ socket[5C], Muxes_and_ADC[3C]), Pin19 (bidir, see Analog_Switch_Array_and_ZIF_ socket[2C], Muxes_and_ADC[3C]), Pin19 (bidir, see Analog_Switch_Array_and_ZIF_ socket[5C], Muxes_and_ADC[3C]), Pin20 (bidir, see Analog_Switch_Array_and_ZIF_ socket[2C], Muxes_and_ADC[3C]), Pin20 (bidir, see Analog_Switch_Array_and_ZIF_ socket[5C], Muxes_and_ADC[3C])

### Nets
5V_ISO: C16.1 C16.2 C17.1 C17.2 C18.1 C18.2 C19.1 C20.1 C21.1 C21.2 C22.1 C22.2 C23.1 C23.2 C24.1 C25.1 C26.1 C26.2 C27.1 C27.2 U8.1(VSS) U8.24(VDD) U8.28(A0) U8.29(A1) U8.30(A2) U8.32(GND) U8.HTAB(EPAD) U9.1(VSS) U9.24(VDD) U9.29(A1) U9.30(A2) U9.32(GND) U9.HTAB(EPAD)  [also labelled GND_ISO]
VDD: C19.2 C20.2 C24.2 C25.2 R19.2 R22.2 R23.2 R24.2 U8.25(VL) U9.25(VL) U9.28(A0)
NetC6_2: U8.10(Y1) U9.10(Y1) ; port 2.5V
NetC7_2: U8.11(Y2) U9.11(Y2) ; port 3.3V
NetC8_2: U8.12(Y3) U9.12(Y3) ; port 4V
NetC9_2: U8.13(Y4) U9.13(Y4) ; port 4.5V
NetC10_2: U8.9(Y0) U9.9(Y0) ; port 1.8V
NetJ3_1: J3.1 U8.3(X0) ; port Pin1
NetJ3_2: J3.2 U8.4(X1) ; port Pin2
NetJ3_3: J3.3 U8.5(X2) ; port Pin3
NetJ3_4: J3.4 U8.6(X3) ; port Pin4
NetJ3_5: J3.5 U8.7(X4) ; port Pin5
NetJ3_6: J3.6 U8.8(X5) ; port Pin6
NetJ3_7: J3.7 U8.17(X6) ; port Pin7
NetJ3_8: J3.8 U8.18(X7) ; port Pin8
NetJ3_9: J3.9 U8.19(X8) ; port Pin9
NetJ3_10: J3.10 U8.20(X9) ; port Pin10
NetJ3_11: J3.11 U9.3(X0) ; port Pin11
NetJ3_12: J3.12 U9.4(X1) ; port Pin12
NetJ3_13: J3.13 U9.5(X2) ; port Pin13
NetJ3_14: J3.14 U9.6(X3) ; port Pin14
NetJ3_15: J3.15 U9.7(X4) ; port Pin15
NetJ3_16: J3.16 U9.8(X5) ; port Pin16
NetJ3_17: J3.17 U9.17(X6) ; port Pin17
NetJ3_18: J3.18 U9.18(X7) ; port Pin18
NetJ3_19: J3.19 U9.19(X8) ; port Pin19
NetJ3_20: J3.20 U9.20(X9) ; port Pin20
NetR19_1: R19.1 U8.31(*RESET)
NetR20_1: R20.1 R23.1 U8.27(SCL) U9.27(SCL) ; port I2C1_SCL
NetR20_2: R20.2 R21.1 R21.2 R24.1 U8.26(SDA) U9.26(SDA) ; port I2C1_SDA
NetR22_1: R22.1 U9.31(*RESET)

Not connected (* = marked no-connect by the designer): U8 2(NC) 14(Y5) 15(Y6) 16(Y7) 21(X10) 22(X11) 23(NC); U9 2(NC) 14(Y5) 15(Y6) 16(Y7) 21(X10) 22(X11) 23(NC)

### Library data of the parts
C16 C18 C19 C22 C24 C26 = CMP-001-063573-1: CAP CER 1206 0.1F 16V ULTRA STAB
C17 C20 C21 C23 C25 C27 = CMP-001-046966-1: CAP CER 10UF 10V X5R 0603
J3 = CMP-05380-000001-1: CONN IC DIP SOCKET ZIF 20POS GLD; Manufacturer: 3M; Is Female: yes; Standoff Height: 0.38mm; Conn Orientation: Vertical; Number Of Contacts: 20; Conn Gender: Female; Socket Package: DIP20; Pitch: 2.54mm; Current Rating: 1A
R19 R22 = CMP-009-026965-1: RES 10K OHM 0.1% 1/16W 0402
R20 R21 R23 R24 = CMP-009-093445-1: RES 2.2K OHM 10% 1/2W 1210
U8 U9 = CMP-011-00018-1: I2C CMOS 8 X 12 Analog Switch Array with Dual/Single Supplies; Manufacturer_Name: Analog Devices Inc

## Sheet Muxes_and_ADC.SchDoc
size 431 x 279 mm; Organization: ORGANIZATION; Address1: ADDRESS 1; Address2: ADDRESS 2; Address3: ADDRESS 3; Address4: ADDRESS 4; Revision: -; SheetNumber: 4; SheetTotal: 4; ENG_APP_DATE: --/--/--; DSN_APP_DATE: --/--/--; CHK_APP_DATE: --/--/--
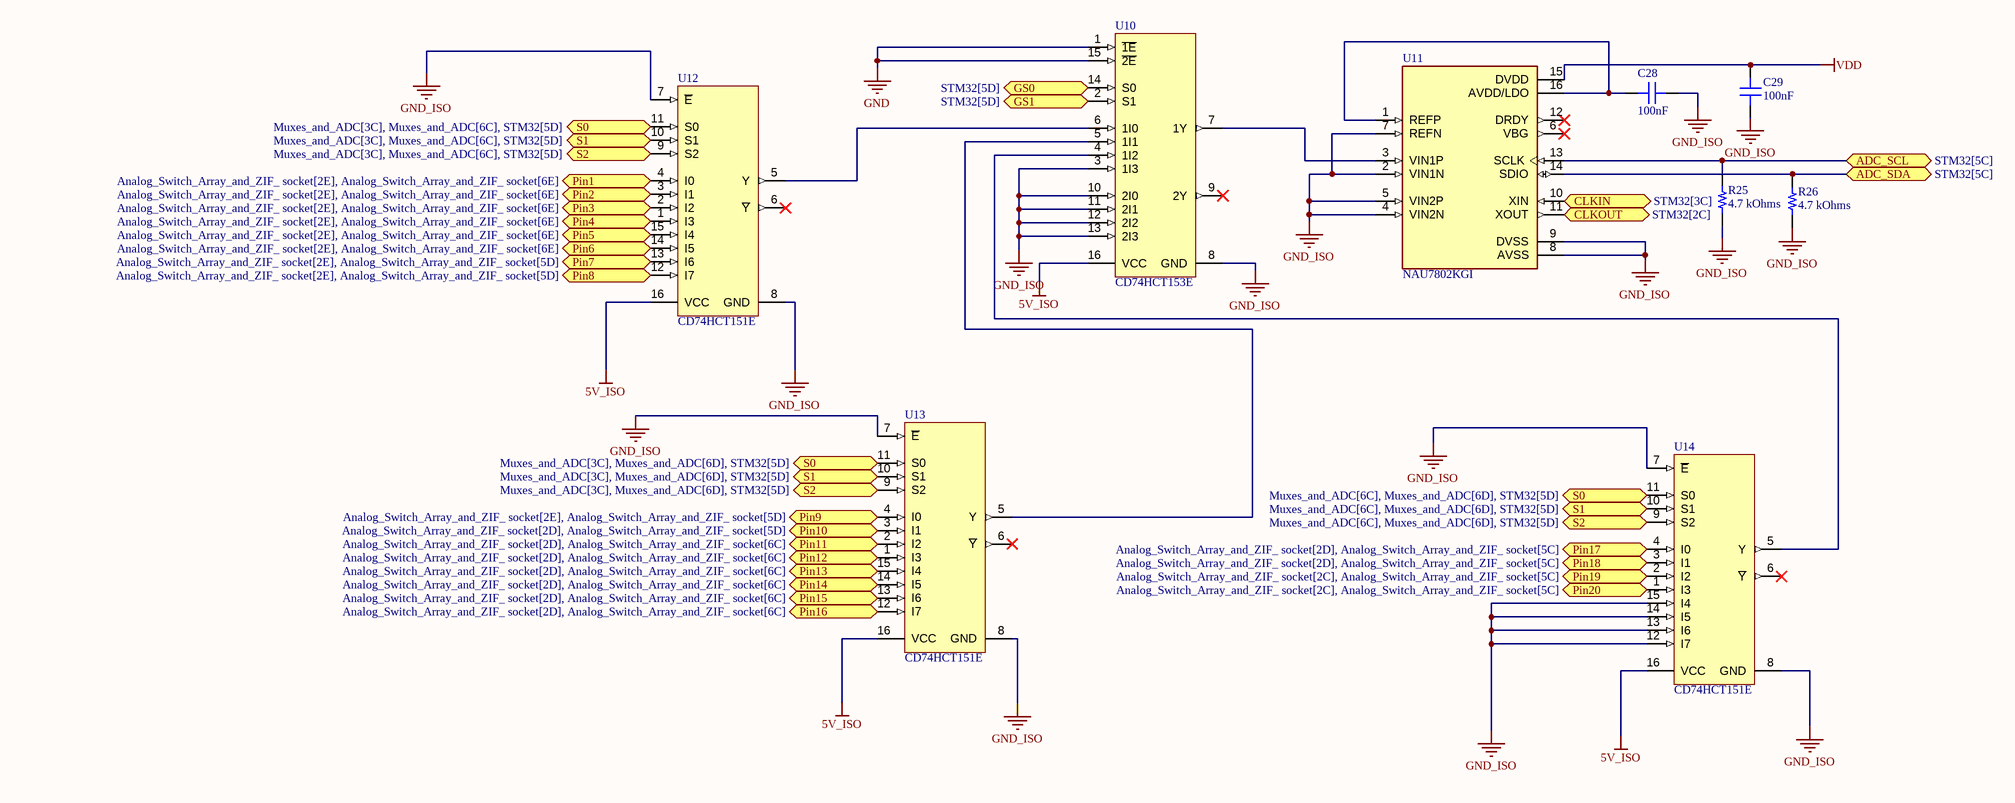
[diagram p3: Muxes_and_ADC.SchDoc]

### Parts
C28  value 100nF  [CAP 1206_3216 - 0.8MM]  (hidden comment: C1206X104G4HAC7800)
C29  value 100nF  [CAP 1206_3216 - 0.8MM]  (hidden comment: C1206X104G4HAC7800)
R25  value 4.7 kOhms  [RES 0603_1608]  (hidden comment: KTR03EZPF4701)
R26  value 4.7 kOhms  [RES 0603_1608]  (hidden comment: KTR03EZPF4701)
U10  CD74HCT153E  [N0016A]
U11  NAU7802KGI  [DIP792W45P254L1904H533Q16]
U12  CD74HCT151E  [N0016A]
U13  CD74HCT151E  [N0016A]
U14  CD74HCT151E  [N0016A]

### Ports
ADC_SCL (bidir, see STM32[5C]), ADC_SDA (bidir, see STM32[5C]), CLKIN (bidir, see STM32[3C]), CLKOUT (bidir, see STM32[2C]), GS0 (bidir, see STM32[5D]), GS1 (bidir, see STM32[5D]), Pin1 (bidir, see Analog_Switch_Array_and_ZIF_ socket[2E], Analog_Switch_Array_and_ZIF_ socket[6E]), Pin2 (bidir, see Analog_Switch_Array_and_ZIF_ socket[2E], Analog_Switch_Array_and_ZIF_ socket[6E]), Pin3 (bidir, see Analog_Switch_Array_and_ZIF_ socket[2E], Analog_Switch_Array_and_ZIF_ socket[6E]), Pin4 (bidir, see Analog_Switch_Array_and_ZIF_ socket[2E], Analog_Switch_Array_and_ZIF_ socket[6E]), Pin5 (bidir, see Analog_Switch_Array_and_ZIF_ socket[2E], Analog_Switch_Array_and_ZIF_ socket[6E]), Pin6 (bidir, see Analog_Switch_Array_and_ZIF_ socket[2E], Analog_Switch_Array_and_ZIF_ socket[6E]), Pin7 (bidir, see Analog_Switch_Array_and_ZIF_ socket[2E], Analog_Switch_Array_and_ZIF_ socket[5D]), Pin8 (bidir, see Analog_Switch_Array_and_ZIF_ socket[2E], Analog_Switch_Array_and_ZIF_ socket[5D]), Pin9 (bidir, see Analog_Switch_Array_and_ZIF_ socket[2E], Analog_Switch_Array_and_ZIF_ socket[5D]), Pin10 (bidir, see Analog_Switch_Array_and_ZIF_ socket[2D], Analog_Switch_Array_and_ZIF_ socket[5D]), Pin11 (bidir, see Analog_Switch_Array_and_ZIF_ socket[2D], Analog_Switch_Array_and_ZIF_ socket[6C]), Pin12 (bidir, see Analog_Switch_Array_and_ZIF_ socket[2D], Analog_Switch_Array_and_ZIF_ socket[6C]), Pin13 (bidir, see Analog_Switch_Array_and_ZIF_ socket[2D], Analog_Switch_Array_and_ZIF_ socket[6C]), Pin14 (bidir, see Analog_Switch_Array_and_ZIF_ socket[2D], Analog_Switch_Array_and_ZIF_ socket[6C]), Pin15 (bidir, see Analog_Switch_Array_and_ZIF_ socket[2D], Analog_Switch_Array_and_ZIF_ socket[6C]), Pin16 (bidir, see Analog_Switch_Array_and_ZIF_ socket[2D], Analog_Switch_Array_and_ZIF_ socket[6C]), Pin17 (bidir, see Analog_Switch_Array_and_ZIF_ socket[2D], Analog_Switch_Array_and_ZIF_ socket[5C]), Pin18 (bidir, see Analog_Switch_Array_and_ZIF_ socket[2D], Analog_Switch_Array_and_ZIF_ socket[5C]), Pin19 (bidir, see Analog_Switch_Array_and_ZIF_ socket[2C], Analog_Switch_Array_and_ZIF_ socket[5C]), Pin20 (bidir, see Analog_Switch_Array_and_ZIF_ socket[2C], Analog_Switch_Array_and_ZIF_ socket[5C]), S0 (bidir, see Muxes_and_ADC[3C], Muxes_and_ADC[6C], STM32[5D]), S0 (bidir, see Muxes_and_ADC[3C], Muxes_and_ADC[6D], STM32[5D]), S0 (bidir, see Muxes_and_ADC[6C], Muxes_and_ADC[6D], STM32[5D]), S1 (bidir, see Muxes_and_ADC[3C], Muxes_and_ADC[6C], STM32[5D]), S1 (bidir, see Muxes_and_ADC[3C], Muxes_and_ADC[6D], STM32[5D]), S1 (bidir, see Muxes_and_ADC[6C], Muxes_and_ADC[6D], STM32[5D]), S2 (bidir, see Muxes_and_ADC[3C], Muxes_and_ADC[6C], STM32[5D]), S2 (bidir, see Muxes_and_ADC[3C], Muxes_and_ADC[6D], STM32[5D]), S2 (bidir, see Muxes_and_ADC[6C], Muxes_and_ADC[6D], STM32[5D])

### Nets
5V_ISO: C28.1 C29.2 R25.1 R26.1 U10.3(1I3) U10.8(GND) U10.10(2I0) U10.11(2I1) U10.12(2I2) U10.13(2I3) U10.16(VCC) U11.2(VIN1N) U11.4(VIN2N) U11.5(VIN2P) U11.7(REFN) U11.8(AVSS) U11.9(DVSS) U12.7(~{E}) U12.8(GND) U12.16(VCC) U13.7(~{E}) U13.8(GND) U13.16(VCC) U14.7(~{E}) U14.8(GND) U14.12(I7) U14.13(I6) U14.14(I5) U14.15(I4) U14.16(VCC)  [also labelled GND_ISO]
GND: U10.1(~{1E}) U10.15(~{2E})
VDD: C29.1 U11.15(DVDD)
NetC11_2: U11.11(XOUT) ; port CLKOUT
NetC12_2: U11.10(XIN) ; port CLKIN
NetC28_2: C28.2 U11.1(REFP) U11.16(AVDD/LDO)
NetJ3_1: U12.4(I0) ; port Pin1
NetJ3_2: U12.3(I1) ; port Pin2
NetJ3_3: U12.2(I2) ; port Pin3
NetJ3_4: U12.1(I3) ; port Pin4
NetJ3_5: U12.15(I4) ; port Pin5
NetJ3_6: U12.14(I5) ; port Pin6
NetJ3_7: U12.13(I6) ; port Pin7
NetJ3_8: U12.12(I7) ; port Pin8
NetJ3_9: U13.4(I0) ; port Pin9
NetJ3_10: U13.3(I1) ; port Pin10
NetJ3_11: U13.2(I2) ; port Pin11
NetJ3_12: U13.1(I3) ; port Pin12
NetJ3_13: U13.15(I4) ; port Pin13
NetJ3_14: U13.14(I5) ; port Pin14
NetJ3_15: U13.13(I6) ; port Pin15
NetJ3_16: U13.12(I7) ; port Pin16
NetJ3_17: U14.4(I0) ; port Pin17
NetJ3_18: U14.3(I1) ; port Pin18
NetJ3_19: U14.2(I2) ; port Pin19
NetJ3_20: U14.1(I3) ; port Pin20
NetR25_2: R25.2 U11.13(SCLK) ; port ADC_SCL
NetR26_2: R26.2 U11.14(SDIO) ; port ADC_SDA
NetU7_18: U12.11(S0) U13.11(S0) U14.11(S0) ; port S0
NetU7_19: U12.10(S1) U13.10(S1) U14.10(S1) ; port S1
NetU7_20: U12.9(S2) U13.9(S2) U14.9(S2) ; port S2
NetU7_22: U10.2(S1) ; port GS1
NetU10_4: U10.4(1I2) U14.5(Y)
NetU10_5: U10.5(1I1) U13.5(Y)
NetU10_6: U10.6(1I0) U12.5(Y)
NetU10_7: U10.7(1Y) U11.3(VIN1P)
NetU10_14: U10.14(S0) ; port GS0

Not connected (* = marked no-connect by the designer): U10 9(2Y)*; U11 6(VBG)* 12(DRDY)*; U12 6(~{Y})*; U13 6(~{Y})*; U14 6(~{Y})*

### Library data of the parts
C28 C29 = CMP-001-063573-1: CAP CER 1206 0.1F 16V ULTRA STAB
R25 R26 = CMP-009-042855-1: RES SMD 4.7K OHM 1% 1/10W 0603
U10 = CMP-1633-00665-2: High Speed CMOS Logic Dual 4-Input Multiplexers, N0016A, TUBE; Manufacturer: Texas Instruments; VCC(Max)(V): 5.5; Voltage(Nom)(V): 5; ICC @ Nom Voltage(Max)(mA): 0.08; Configuration: 4：1; Rating: Catalog; tpd @ Nom Voltage(Max)(ns): 43; F @ Nom Voltage(Max)(Mhz): 25; VCC(Min)(V): 4.5; Function: Encoder/Multiplexer; Technology Family: HCT; Schmitt Trigger: No; Bits(#): 4; Input Type: TTL; Channels(#): 2; Output Drive (IOL/IOH)(Max)(mA): 4/-4
U11 = CMP-00254-1: 24 Bit Analog to Digital Converter 2 Input 1 Sigma-Delta 16-PDIP; MF: Nuvoton Technology Corporation of America
U12-U14 = CMP-1633-00678-2: High Speed CMOS Logic 8-Input Multiplexer, N0016A, TUBE; Manufacturer: Texas Instruments; Output Drive (IOL/IOH)(Max)(mA): 4/-4; Technology Family: HCT; Input Type: TTL; F @ Nom Voltage(Max)(Mhz): 25; Rating: Catalog; Bits(#): 8; VCC(Min)(V): 4.5; VCC(Max)(V): 5.5; Schmitt Trigger: No; tpd @ Nom Voltage(Max)(ns): 48; ICC @ Nom Voltage(Max)(mA): 0.08; Channels(#): 1; Function: Encoder/Multiplexer; Configuration: 8：1; Voltage(Nom)(V): 5

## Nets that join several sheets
5V_ISO: USB_to_UART (35 pins), STM32 (30 pins), Analog_Switch_Array_and_ZIF_ socket (33 pins), Muxes_and_ADC (30 pins)
VDD: USB_to_UART (6 pins), STM32 (C14.2 C15.2 J2.1 U7.8), Analog_Switch_Array_and_ZIF_ socket (11 pins), Muxes_and_ADC (C29.1 U11.15)
NetC6_2: STM32 (C6.2 R1.2 R7.2 U2.3), Analog_Switch_Array_and_ZIF_ socket (U8.10 U9.10)
NetC7_2: STM32 (C7.2 R4.2 R8.2 U4.3), Analog_Switch_Array_and_ZIF_ socket (U8.11 U9.11)
NetC8_2: STM32 (C8.2 R5.2 R9.2 U3.3), Analog_Switch_Array_and_ZIF_ socket (U8.12 U9.12)
NetC9_2: STM32 (C9.2 R6.2 R10.2 U5.3), Analog_Switch_Array_and_ZIF_ socket (U8.13 U9.13)
NetC10_2: STM32 (C10.2 R11.2 R16.2 U6.3), Analog_Switch_Array_and_ZIF_ socket (U8.9 U9.9)
NetC11_2: STM32 (C11.2 U7.11 Y1.3), Muxes_and_ADC (U11.11)
NetC12_2: STM32 (C12.2 U7.10 Y1.1), Muxes_and_ADC (U11.10)
NetD4_2: USB_to_UART (D4.2 U1.25), STM32 (U7.37)
NetD5_2: USB_to_UART (D5.2 U1.26), STM32 (U7.42)
NetJ3_1: Analog_Switch_Array_and_ZIF_ socket (J3.1 U8.3), Muxes_and_ADC (U12.4)
NetJ3_2: Analog_Switch_Array_and_ZIF_ socket (J3.2 U8.4), Muxes_and_ADC (U12.3)
NetJ3_3: Analog_Switch_Array_and_ZIF_ socket (J3.3 U8.5), Muxes_and_ADC (U12.2)
NetJ3_4: Analog_Switch_Array_and_ZIF_ socket (J3.4 U8.6), Muxes_and_ADC (U12.1)
NetJ3_5: Analog_Switch_Array_and_ZIF_ socket (J3.5 U8.7), Muxes_and_ADC (U12.15)
NetJ3_6: Analog_Switch_Array_and_ZIF_ socket (J3.6 U8.8), Muxes_and_ADC (U12.14)
NetJ3_7: Analog_Switch_Array_and_ZIF_ socket (J3.7 U8.17), Muxes_and_ADC (U12.13)
NetJ3_8: Analog_Switch_Array_and_ZIF_ socket (J3.8 U8.18), Muxes_and_ADC (U12.12)
NetJ3_9: Analog_Switch_Array_and_ZIF_ socket (J3.9 U8.19), Muxes_and_ADC (U13.4)
NetJ3_10: Analog_Switch_Array_and_ZIF_ socket (J3.10 U8.20), Muxes_and_ADC (U13.3)
NetJ3_11: Analog_Switch_Array_and_ZIF_ socket (J3.11 U9.3), Muxes_and_ADC (U13.2)
NetJ3_12: Analog_Switch_Array_and_ZIF_ socket (J3.12 U9.4), Muxes_and_ADC (U13.1)
NetJ3_13: Analog_Switch_Array_and_ZIF_ socket (J3.13 U9.5), Muxes_and_ADC (U13.15)
NetJ3_14: Analog_Switch_Array_and_ZIF_ socket (J3.14 U9.6), Muxes_and_ADC (U13.14)
NetJ3_15: Analog_Switch_Array_and_ZIF_ socket (J3.15 U9.7), Muxes_and_ADC (U13.13)
NetJ3_16: Analog_Switch_Array_and_ZIF_ socket (J3.16 U9.8), Muxes_and_ADC (U13.12)
NetJ3_17: Analog_Switch_Array_and_ZIF_ socket (J3.17 U9.17), Muxes_and_ADC (U14.4)
NetJ3_18: Analog_Switch_Array_and_ZIF_ socket (J3.18 U9.18), Muxes_and_ADC (U14.3)
NetJ3_19: Analog_Switch_Array_and_ZIF_ socket (J3.19 U9.19), Muxes_and_ADC (U14.2)
NetJ3_20: Analog_Switch_Array_and_ZIF_ socket (J3.20 U9.20), Muxes_and_ADC (U14.1)
NetR20_1: STM32 (U7.60), Analog_Switch_Array_and_ZIF_ socket (R20.1 R23.1 U8.27 U9.27)
NetR20_2: STM32 (U7.61), Analog_Switch_Array_and_ZIF_ socket (6 pins)
NetR25_2: STM32 (U7.30), Muxes_and_ADC (R25.2 U11.13)
NetR26_2: STM32 (U7.31), Muxes_and_ADC (R26.2 U11.14)
NetU7_18: STM32 (U7.18), Muxes_and_ADC (U12.11 U13.11 U14.11)
NetU7_19: STM32 (U7.19), Muxes_and_ADC (U12.10 U13.10 U14.10)
NetU7_20: STM32 (U7.20), Muxes_and_ADC (U12.9 U13.9 U14.9)
NetU7_22: STM32 (U7.22), Muxes_and_ADC (U10.2)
